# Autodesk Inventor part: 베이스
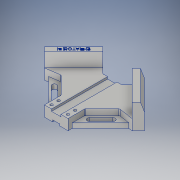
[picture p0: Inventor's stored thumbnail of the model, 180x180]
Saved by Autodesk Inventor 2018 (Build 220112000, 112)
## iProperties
Created: 2020-05
Part Number: 베이스
Material: 알루미늄 6061
Document SubType Name: Modeling
Designer: theplan76
Density: 2.7 g/cm^3
Appearance: 알루미늄 - 평지
Mass: 571.538 g
Surface Area: 407.236 cm^2
Volume: 211.681 cm^3
Author: theplan76
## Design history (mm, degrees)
sketch "스케치1"
  geometry: L1 (0, 0)-(84.853, -84.853); L2 (84.853, -84.853)-(0, -169.706); L3 (0, -169.706)-(-84.853, -84.853); L4 (-84.853, -84.853)-(0, 0); L5 (0, -169.706)-(35.355, -134.35); L6 (35.355, -134.35)-(0, -98.995); L7 (0, -98.995)-(-35.355, -134.35); L8 (-35.355, -134.35)-(0, -169.706); L9 (16.005, -115)-(-16.005, -115); L10 (20, -20)-(-20, -20)
  constraints: 20 end point, 5 parallel, 5 point on line, 4 perpendicular, 1 horizontal, 1 vertical alignment
  dimensions: "d0" = 120 distance of L2.end L3.end; "d1" = 50 distance of L5.end L6.end; "d2" = 95 distance between parallel lines of L10 L9; "d3" = 20 distance from line of L1.start L10
extrude "돌출1" new body sketch "스케치1" distance "d4" = 18; taper "d5" = 0 deg
sketch "스케치2"
  geometry: L1 (-35.355, 134.35)-(-84.853, 84.853) reference; L2 (84.853, 84.853)-(35.355, 134.35) reference; L3 (-74.246, 74.246)-(-24.749, 123.744); L4 (28.632, 127.627)-(78.13, 78.13); L5 (20, 20)-(84.853, 84.853) reference; L6 (-74.246, 74.246)-(-49.497, 77.782); L7 (-49.497, 77.782)-(-20, 48.284); L8 (-20, 20)-(20, 20) reference; L9 (-20, 48.284)-(-20, 20); L10 (-84.853, 84.853)-(-20, 20) reference; L11 (-16.005, 115)-(-35.355, 134.35) reference; L12 (35.355, 134.35)-(16.005, 115) reference; L13 (-68.059, 75.13)-(-20, 27.071); L14 (-49.497, 66.468)-(-29.698, 46.669); L15 (-52.326, 63.64)-(-32.527, 43.841); L16 (-26.87, 49.497)-(-46.669, 69.296); A1 r 4 centre (-49.497, 66.468) between (-46.669, 69.296) and (-52.326, 63.64); A2 r 4 centre (-29.698, 46.669) between (-32.527, 43.841) and (-26.87, 49.497); 2 further points
  constraints: 20 end point, 5 parallel, 5 point on line, 4 point on circle, 4 tangent, 2 centre point, 1 midpoint, 1 perpendicular
  dimensions: "d6" = 15 distance between parallel lines of L1 L3; "d7" = 5 distance between parallel lines of L13 L10; "d8" = 12 distance from line of point (-39.598, 56.569) L10; "d9" = 20 distance between parallel lines of L7 L10; "d10" = 30 distance from line of L6.end L1; "d11" = 38 distance from line of L14.start L1; "d12" = 28 distance of L14.end L14.start; "d13" = 8 distance between parallel lines of L15 L16
extrude "돌출2" join sketch "스케치2" distance "d14" = 24; taper "d15" = 0 deg
extrude "돌출3" cut sketch "스케치2" distance "d16" = 10; taper "d17" = 0 deg
extrude "돌출4" cut sketch "스케치2" distance "d18" = 54.5; taper "d19" = 0 deg
extrude "돌출5" cut sketch "스케치2" distance "d20" = 54.5; taper "d21" = 0 deg
sketch "스케치3"
  geometry: L1 (15, 0)-(15, 18) reference; L2 (15, 18)-(15, 42) reference; L3 (0, 42)-(15, 42) reference; L4 (0, 0)-(0, 42) reference; L5 (0, 0)-(15, 0) reference; L6 (0, 42)-(0, 0) reference; L7 (0, 27)-(5, 42); L8 (0, 0)-(0, 42) reference; L9 (0, 27)-(0, 42); L10 (0, 42)-(5, 42); L11 (0, 42)-(15, 42) reference; 1 further point
  constraints: 6 end point, 2 collinear, 2 point on line
  dimensions: "d22" = 5 distance from line of L4 L7.end; "d23" = 15 distance from line of L7.start L3
extrude "돌출6" cut sketch "스케치3" distance "d24" = 81.25; taper "d25" = 0 deg
sketch "스케치4"
  geometry: L1 (12, 18)-(28, 18); L2 (28, 18)-(28, 14.5); L3 (28, 14.5)-(12, 14.5); L4 (12, 14.5)-(12, 18); L5 (3.995, 0)-(36.005, 0) reference; L6 (14, 0)-(26, 0); L7 (26, 0)-(26, 3); L8 (26, 3)-(14, 3); L9 (14, 3)-(14, 0); L10 (0, 18)-(40, 18) reference; 7 further points
  constraints: 16 end point, 4 parallel, 3 midpoint, 2 horizontal, 2 perpendicular, 2 vertical alignment, 1 collinear, 1 point on line, 2 other
  dimensions: "d26" = 16 distance between parallel lines of L2 L4; "d27" = 12 distance between parallel lines of L7 L9; "d28" = 3 distance between parallel lines of L5 L8; "d29" = 3.5 distance between parallel lines of L3 L10
extrude "돌출7" cut sketch "스케치4" distance "d30" = 113.5; taper "d31" = 0 deg
sketch "스케치5"
  geometry: L1 (8, 20)-(20, 20) reference; L2 (0, 0)-(0, 116.988); 4 further points
  constraints: 2 end point, 2 horizontal alignment, 2 symmetric about line, 2 vertical alignment, 1 vertical
  dimensions: "d32" = 6 distance from line of point (14, 26) L1; "d33" = 12 distance of point (14, 26) point (14, 38); "d34" = 28 distance of point (14, 26) point (-14, 26)
hole "구멍1" sketch "스케치5" at (-14, 38), (-14, 26), (14, 38), (14, 26) diameter "d35" = 4.5; stored, may be unused: countersink angle "d39" = 90 deg, drill point angle "d41" = 0 deg; dims "d36" = 6, "d37" = 4, "d38" = 2, "d40" = 8
sketch "스케치6"
  geometry: C1 r 2.25 at (-14, -38) reference; C2 r 2.25 at (-14, -26) reference; C3 r 2.25 at (14, -38) reference; C4 r 2.25 at (14, -38) reference; C5 r 2.25 at (14, -26) reference; C6 r 4 at (-14, -26); C7 r 4 at (-14, -38); C8 r 2.25 at (14, -26) reference; C9 r 4 at (14, -26); C10 r 2.25 at (14, -38) reference; C11 r 4 at (14, -38); 1 further point
  constraints: 4 centre point, 4 coincident, 3 equal radius
  dimensions: "d42" = 8 diameter of C6
extrude "돌출8" cut sketch "스케치6" distance "d43" = 10; taper "d44" = 0 deg
fillet "모깎기1" dims "d45" = 3
fillet "모깎기2" dims "d46" = 3
sketch "스케치7"
  geometry: L1 (-74.246, 74.246)-(-24.749, 123.744) reference; L2 (-24.749, 123.744)-(-31.82, 130.815) reference; 2 further points
  constraints: 1 other
  dimensions: "d47" = 35 distance from line of point (-53.033, 102.53) L2; "d48" = 5 distance from line of L1 point (-53.033, 102.53)
feature "엠보싱1" sketch "스케치7" dims "d0" = 120, "d1" = 50, "d2" = 95, "d3" = 20, "d49" = 0.5, "d50" = 0
node "솔리드1"
mirror "미러1"
mirror "미러2"
node "투영된 루프1"
node "투영된 루프2"
